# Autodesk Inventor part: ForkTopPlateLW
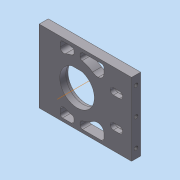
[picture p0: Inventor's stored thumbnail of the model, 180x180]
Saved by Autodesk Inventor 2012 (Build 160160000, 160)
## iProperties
Created: 2010-11
Part Number: ForkTopPlateLW
Document SubType Name: Modeling
Designer: rawdaj
Density: 2.71 g/cm^3
Material: Aluminum-6061
Mass: 125.573 g
Surface Area: 200.82 cm^2
Volume: 46.3371 cm^3
GlobalPropertyList: <PropertyList/>
Author: rawdaj
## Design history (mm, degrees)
sketch "Sketch1"
  geometry: L1 (0, 0)-(0, 76.2); L2 (0, 76.2)-(96.838, 76.2); L3 (96.838, 76.2)-(96.837, 0); L4 (96.837, 0)-(0, 0); C1 r 18.161 at (39.687, 38.1)
  constraints: 8 end point, 2 perpendicular, 1 centre point, 1 parallel, 1 vertical
  dimensions: "d37" = 36.322 diameter of C1; "d51" = 76.2 distance of L2.end L3.end; "d87" = 96.8375 distance of L1.end L2.end; "d104" = 38.1 distance from line of L4 C1.centre; "d106" = 57.15 distance from line of C1.centre L3
extrude "Extrusion1" new body sketch "Sketch1" distance "d15" = 9.525; taper "d16" = 0 deg
sketch "Sketch2"
  geometry: L1 (9.525, 0)-(9.525, 76.2) reference; L2 (0, 76.2)-(9.525, 76.2) reference; L3 (0, 0)-(9.525, 0) reference; L4 (4.763, 76.2)-(4.763, 0); 3 further points
  constraints: 3 midpoint, 2 end point, 1 point on line
  dimensions: "d55" = 4.7625 distance from line of L1 point (4.763, 66.675); "d56" = 9.525 distance from line of L2 point (4.763, 66.675); "d57" = 38.1 distance from line of L2 point (4.763, 38.1); "d88" = 9.525 distance from line of L3 point (4.763, 9.525)
sketch "Sketch3"
  geometry: L1 (-9.525, 76.2)-(-9.525, 0) reference; L2 (0, 76.2)-(-9.525, 76.2) reference; L3 (0, 0)-(-9.525, 0) reference; L4 (-4.763, 76.2)-(-4.763, 0); 3 further points
  constraints: 3 midpoint, 2 end point
  dimensions: "d69" = 38.1 distance from line of L2 point (-4.763, 38.1); "d70" = 9.525 distance from line of L2 point (-4.763, 66.675); "d71" = 4.7625 distance from line of L1 point (-4.763, 66.675); "d89" = 9.525 distance from line of L3 point (-4.763, 9.525)
sketch "Sketch4"
  geometry: C1 r 18.161 at (-39.687, 38.1) reference; C2 r 19.05 at (-39.687, 38.1)
  constraints: 1 centre point, 1 coincident
  dimensions: "d38" = 38.1 diameter of C2
hole "Hole1" sketch "Sketch4" at (-39.687, 38.1) diameter "d39" = 38.1; stored, may be unused: countersink angle "d43" = 82 deg, drill point angle "d45" = 0 deg; dims "d40" = 19.05, "d41" = 9.525, "d42" = 6.35, "d44" = 3.175
hole "Hole2" sketch "Sketch2" diameter "d60" = 3.9624; stored, may be unused: countersink angle "d64" = 82 deg, drill point angle "d66" = 118 deg; dims "d61" = 12.7, "d62" = 9.525, "d63" = 6.35, "d65" = 19.05
hole "Hole3" sketch "Sketch3" diameter "d72" = 3.9624; stored, may be unused: countersink angle "d76" = 82 deg, drill point angle "d78" = 118 deg; dims "d73" = 12.7, "d74" = 9.525, "d75" = 6.35, "d77" = 19.05
sketch "Sketch6"
  geometry: L1 (30.162, 55.467)-(49.212, 55.467); L2 (49.212, 55.467)-(49.212, 56.261); L3 (49.212, 56.261)-(30.162, 56.261); L4 (30.162, 56.261)-(30.162, 55.467); C1 r 18.161 at (39.687, 38.1) reference
  constraints: 8 end point, 2 parallel, 1 horizontal, 1 perpendicular
  dimensions: "d79" = 0.79375 distance between parallel lines of L1 L3; "d80" = 18.161 distance from line of C1.centre L3; "d81" = 19.05 distance between parallel lines of L2 L4; "d82" = 9.525 distance from line of L4 C1.centre
extrude "Extrusion4" join sketch "Sketch6" distance "d83" = 6.35; taper "d84" = 0 deg
fillet "Fillet1" dims "d85" = 6.35
workplane "Work Plane1"
sketch "Sketch9"
  geometry: L1 (0, 0)-(0, 76.2) reference; L2 (96.837, 0)-(0, 0) reference; L3 (0, 76.2)-(96.838, 76.2) reference; L4 (36.512, 70.485)-(36.513, 67.781); L5 (39.687, 76.2)-(39.687, -1.683); L6 (33.972, 73.025)-(24.501, 73.025); L7 (21.961, 70.485)-(21.961, 66.355); L8 (3.175, 53.34)-(3.175, 58.702); L9 (5.715, 61.242)-(13.068, 61.242); L10 (11.482, 50.8)-(5.715, 50.8); L11 (0, 38.1)-(99.963, 38.1); L12 (16.536, 58.86)-(14.846, 60.516); L13 (35.431, 55.467)-(43.944, 55.467) reference; L14 (45.402, 73.025)-(65.389, 73.025); L15 (96.838, 76.2)-(96.837, 0) reference; L16 (67.929, 65.087)-(67.929, 70.485); L17 (42.862, 70.485)-(42.862, 67.781); L18 (67.929, 11.112)-(67.929, 5.715); L19 (3.175, 22.86)-(3.175, 17.498); L20 (11.482, 25.4)-(5.715, 25.4); L21 (16.536, 17.34)-(14.846, 15.684); L22 (5.715, 14.958)-(13.068, 14.958); L23 (45.402, 3.175)-(65.389, 3.175); L24 (42.862, 5.715)-(42.862, 8.419); L25 (36.512, 5.715)-(36.512, 8.419); L26 (33.972, 3.175)-(24.501, 3.175); L27 (21.961, 5.715)-(21.961, 9.845); A1 r 18.161 centre (39.687, 38.1) between (33.142, 55.041) and (46.233, 55.041) reference; A2 r 27.686 centre (39.687, 38.1) between (16.992, 53.957) and (16.744, 53.596); A3 r 27.686 centre (39.687, 38.1) between (34.453, 65.287) and (27.454, 62.937); A4 r 27.686 centre (39.687, 38.1) between (55.903, 60.541) and (44.922, 65.287); A5 r 2.54 centre (5.715, 58.702) between (5.715, 61.242) and (3.175, 58.702); A6 r 2.54 centre (13.068, 58.702) between (14.846, 60.516) and (13.068, 61.242); A7 r 3.81 centre (13.869, 56.139) between (16.992, 53.957) and (16.536, 58.86); A8 r 6.35 centre (11.482, 57.15) between (11.482, 50.8) and (16.744, 53.596); A9 r 2.54 centre (5.715, 53.34) between (3.175, 53.34) and (5.715, 50.8); A10 r 2.54 centre (24.501, 70.485) between (24.501, 73.025) and (21.961, 70.485); A11 r 3.81 centre (25.771, 66.355) between (21.961, 66.355) and (27.454, 62.937); A12 r 2.54 centre (33.972, 67.781) between (34.453, 65.287) and (36.513, 67.781); A13 r 2.54 centre (33.972, 70.485) between (36.512, 70.485) and (33.972, 73.025); A14 r 2.54 centre (45.402, 70.485) between (45.402, 73.025) and (42.862, 70.485); A15 r 2.54 centre (45.402, 67.781) between (42.862, 67.781) and (44.922, 65.287); A16 r 2.54 centre (65.389, 70.485) between (67.929, 70.485) and (65.389, 73.025); A17 r 2.54 centre (65.389, 5.715) between (65.389, 3.175) and (67.929, 5.715); A18 r 27.686 centre (39.687, 38.1) between (16.744, 22.604) and (16.992, 22.243); A19 r 2.54 centre (5.715, 22.86) between (5.715, 25.4) and (3.175, 22.86); A20 r 6.35 centre (11.482, 19.05) between (16.744, 22.604) and (11.482, 25.4); A21 r 2.54 centre (13.068, 17.498) between (13.068, 14.958) and (14.846, 15.684); A22 r 3.81 centre (13.869, 20.061) between (16.536, 17.34) and (16.992, 22.243); A23 r 2.54 centre (5.715, 17.498) between (3.175, 17.498) and (5.715, 14.958); A24 r 27.686 centre (39.687, 38.1) between (44.922, 10.913) and (55.903, 15.659); A25 r 2.54 centre (45.402, 8.419) between (44.922, 10.913) and (42.862, 8.419); A26 r 2.54 centre (45.402, 5.715) between (42.862, 5.715) and (45.402, 3.175); A27 r 27.686 centre (39.687, 38.1) between (27.454, 13.263) and (34.453, 10.913); A28 r 2.54 centre (33.972, 8.419) between (36.512, 8.419) and (34.453, 10.913); A29 r 2.54 centre (33.972, 5.715) between (33.972, 3.175) and (36.512, 5.715); A30 r 2.54 centre (24.501, 5.715) between (21.961, 5.715) and (24.501, 3.175); A31 r 3.81 centre (25.771, 9.845) between (27.454, 13.263) and (21.961, 9.845); A32 r 9.525 centre (61.481, 68.261) between (55.903, 60.541) and (61.775, 58.741); A33 r 6.35 centre (61.579, 65.087) between (61.775, 58.741) and (67.929, 65.087); A34 r 9.525 centre (61.481, 7.939) between (61.775, 17.459) and (55.903, 15.659); A35 r 6.35 centre (61.579, 11.112) between (67.929, 11.112) and (61.775, 17.459); 22 further points; 1 other entity
  constraints: 77 point on circle, 51 symmetric about line, 44 end point, 34 centre point, 27 point on line, 27 tangent, 4 parallel, 4 perpendicular, 2 coincident, 1 collinear, 1 midpoint, 19 other
  dimensions: "d111" = 3.175 distance between parallel lines of L5 L4; "d112" = 39.6875 distance between parallel lines of L5 L1; "d113" = 3.175 distance between parallel lines of L6 L3; "d114" = 3.175 distance between parallel lines of L1 L8; "d117" = 12.7 distance between parallel lines of L11 L10; "d130" = 3.175 distance between parallel lines of L17 L5; "d131" = 2.54 radius of A5; "d140" = 27.686 radius of A2; "d141" = 6.35 radius of A8; "d142" = 2.54 radius of A9; "d143" = 3.81 radius of A7; "d144" = 2.54 radius of A6; "d145" = 10.44215 distance between parallel lines of L10 L9; "d146" = 27.686 radius of A3; "d147" = 2.54 radius of A13; "d148" = 2.54 radius of A10; "d149" = 14.55194 distance between parallel lines of L4 L7; "d150" = 3.81 radius of A11; "d151" = 2.54 radius of A12; "d152" = 27.686 radius of A4; "d153" = 25.06663 distance between parallel lines of L17 L16; "d154" = 2.54 radius of A14; "d155" = 2.54 radius of A16; "d156" = 2.54 radius of A15; "d171" = 6.35 radius of A33; "d172" = 7.9375 distance from line of A33.centre L14; "d175" = 9.525 radius of A32
extrude "Extrusion7" cut sketch "Sketch9" stored distance "d124" = 25.4; taper "d125" = 0 deg
workaxis "Work Axis2"
workplane "Work Plane2"
workplane "Work Plane3"
sketch "Sketch14"
  geometry: L1 (-96.837, 0)-(-96.838, 76.2) reference; L2 (-84.137, 57.353)-(-77.788, 57.353); L3 (-77.788, 57.353)-(-77.788, 50.597); L4 (-77.788, 50.597)-(-84.137, 50.597); L5 (-84.137, 50.597)-(-84.137, 57.353); L6 (-84.137, 25.603)-(-77.788, 25.603); L7 (-77.788, 25.603)-(-77.788, 18.847); L8 (-77.788, 18.847)-(-84.137, 18.847); L9 (-84.137, 18.847)-(-84.137, 25.603); L10 (-84.137, 53.975)-(-77.787, 53.975); L11 (-84.137, 22.225)-(-77.787, 22.225); L12 (-80.962, 53.975)-(-80.962, 22.225); L13 (-80.962, 38.1)-(-39.687, 38.1); C1 r 19.05 at (-39.687, 38.1) reference; A1 r 3.378 centre (-84.137, 53.975) between (-84.137, 57.353) and (-84.137, 50.597); A2 r 3.378 centre (-77.787, 53.975) between (-77.788, 50.597) and (-77.788, 57.353); A3 r 3.378 centre (-84.137, 22.225) between (-84.137, 25.603) and (-84.137, 18.847); A4 r 3.378 centre (-77.787, 22.225) between (-77.788, 18.847) and (-77.788, 25.603)
  constraints: 24 end point, 8 point on circle, 7 midpoint, 5 parallel, 5 tangent, 4 centre point, 3 horizontal, 2 perpendicular, 1 vertical
  dimensions: "d185" = 6.7564 distance between parallel lines of L8 L6; "d186" = 6.7564 distance between parallel lines of L4 L2; "d187" = 31.75 distance between parallel lines of L10 L11; "d188" = 6.35 distance of L10.start L10.end; "d189" = 12.7 distance between parallel lines of L1 L5
extrude "Extrusion11" cut sketch "Sketch14" stored distance "d190" = 25.4; taper "d191" = 0 deg
sketch "Sketch15"
  geometry: L1 (-84.137, 25.603)-(-77.788, 25.603) reference; L2 (-77.788, 18.847)-(-84.137, 18.847) reference; L3 (-84.137, 57.353)-(-77.788, 57.353) reference; L4 (-77.788, 50.597)-(-84.137, 50.597) reference; L5 (-77.787, 59.725)-(-84.137, 59.725); L6 (-84.137, 48.225)-(-77.787, 48.225); L7 (-77.787, 27.975)-(-84.137, 27.975); L8 (-84.137, 16.475)-(-77.787, 16.475); A1 r 3.378 centre (-84.137, 22.225) between (-84.137, 25.603) and (-84.137, 18.847) reference; A2 r 3.378 centre (-77.787, 22.225) between (-77.788, 18.847) and (-77.788, 25.603) reference; A3 r 3.378 centre (-84.137, 53.975) between (-84.137, 57.353) and (-84.137, 50.597) reference; A4 r 3.378 centre (-77.787, 53.975) between (-77.788, 50.597) and (-77.788, 57.353) reference; A5 r 5.75 centre (-84.137, 53.975) between (-84.137, 59.725) and (-84.137, 48.225); A6 r 5.75 centre (-77.787, 53.975) between (-77.787, 48.225) and (-77.787, 59.725); A7 r 5.75 centre (-84.137, 22.225) between (-84.137, 27.975) and (-84.137, 16.475); A8 r 5.75 centre (-77.787, 22.225) between (-77.787, 16.475) and (-77.787, 27.975)
  constraints: 8 end point, 8 point on circle, 4 centre point, 6 other
  dimensions: "d193" = 11.5 distance between parallel lines of L5 L6; "d194" = 11.5 distance between parallel lines of L8 L7
extrude "Extrusion12" cut sketch "Sketch15" distance "d195" = 4.7625; taper "d196" = 0 deg
body "Solid1"
other parameters: "d109" = -38.1, "d118" = 28.575, "d122" = 6.35, "d123" = 6.35, "d126" = 9.525, "d128" = 27.686, "d157" = 57.15
